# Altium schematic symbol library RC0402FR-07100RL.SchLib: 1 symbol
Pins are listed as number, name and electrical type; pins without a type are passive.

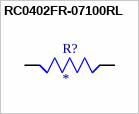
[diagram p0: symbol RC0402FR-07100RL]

## RC0402FR-07100RL
designator R?
100 Ohms Â±1% 0.063W, 1/16W Chip Resistor 0402 (1005 Metric) Moisture Resistant Thick Film; MF: Yageo; MP: RC0402FR-07100RL
footprint RESC1005X40
pins: 1, 2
